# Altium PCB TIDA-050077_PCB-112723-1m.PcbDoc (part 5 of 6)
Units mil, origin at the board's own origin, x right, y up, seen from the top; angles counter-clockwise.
Board outline 3780 x 7750 mil, 16 copper layers (Top Layer, L2-Powet 1, L3-Power 2, L4-Power 3, L5-Power 4, L6-INT 1, L7-INT 2, L8-INT 3, L9-INT 4, L10-INT 5, L11-INT 6, L12-Power 5, L13-Power 6, L14-Power 7, L15-Power 8, Bottom Layer), stack 121.442 mil thick; 381 components, 136 nets, 958 pads, 3470 vias.
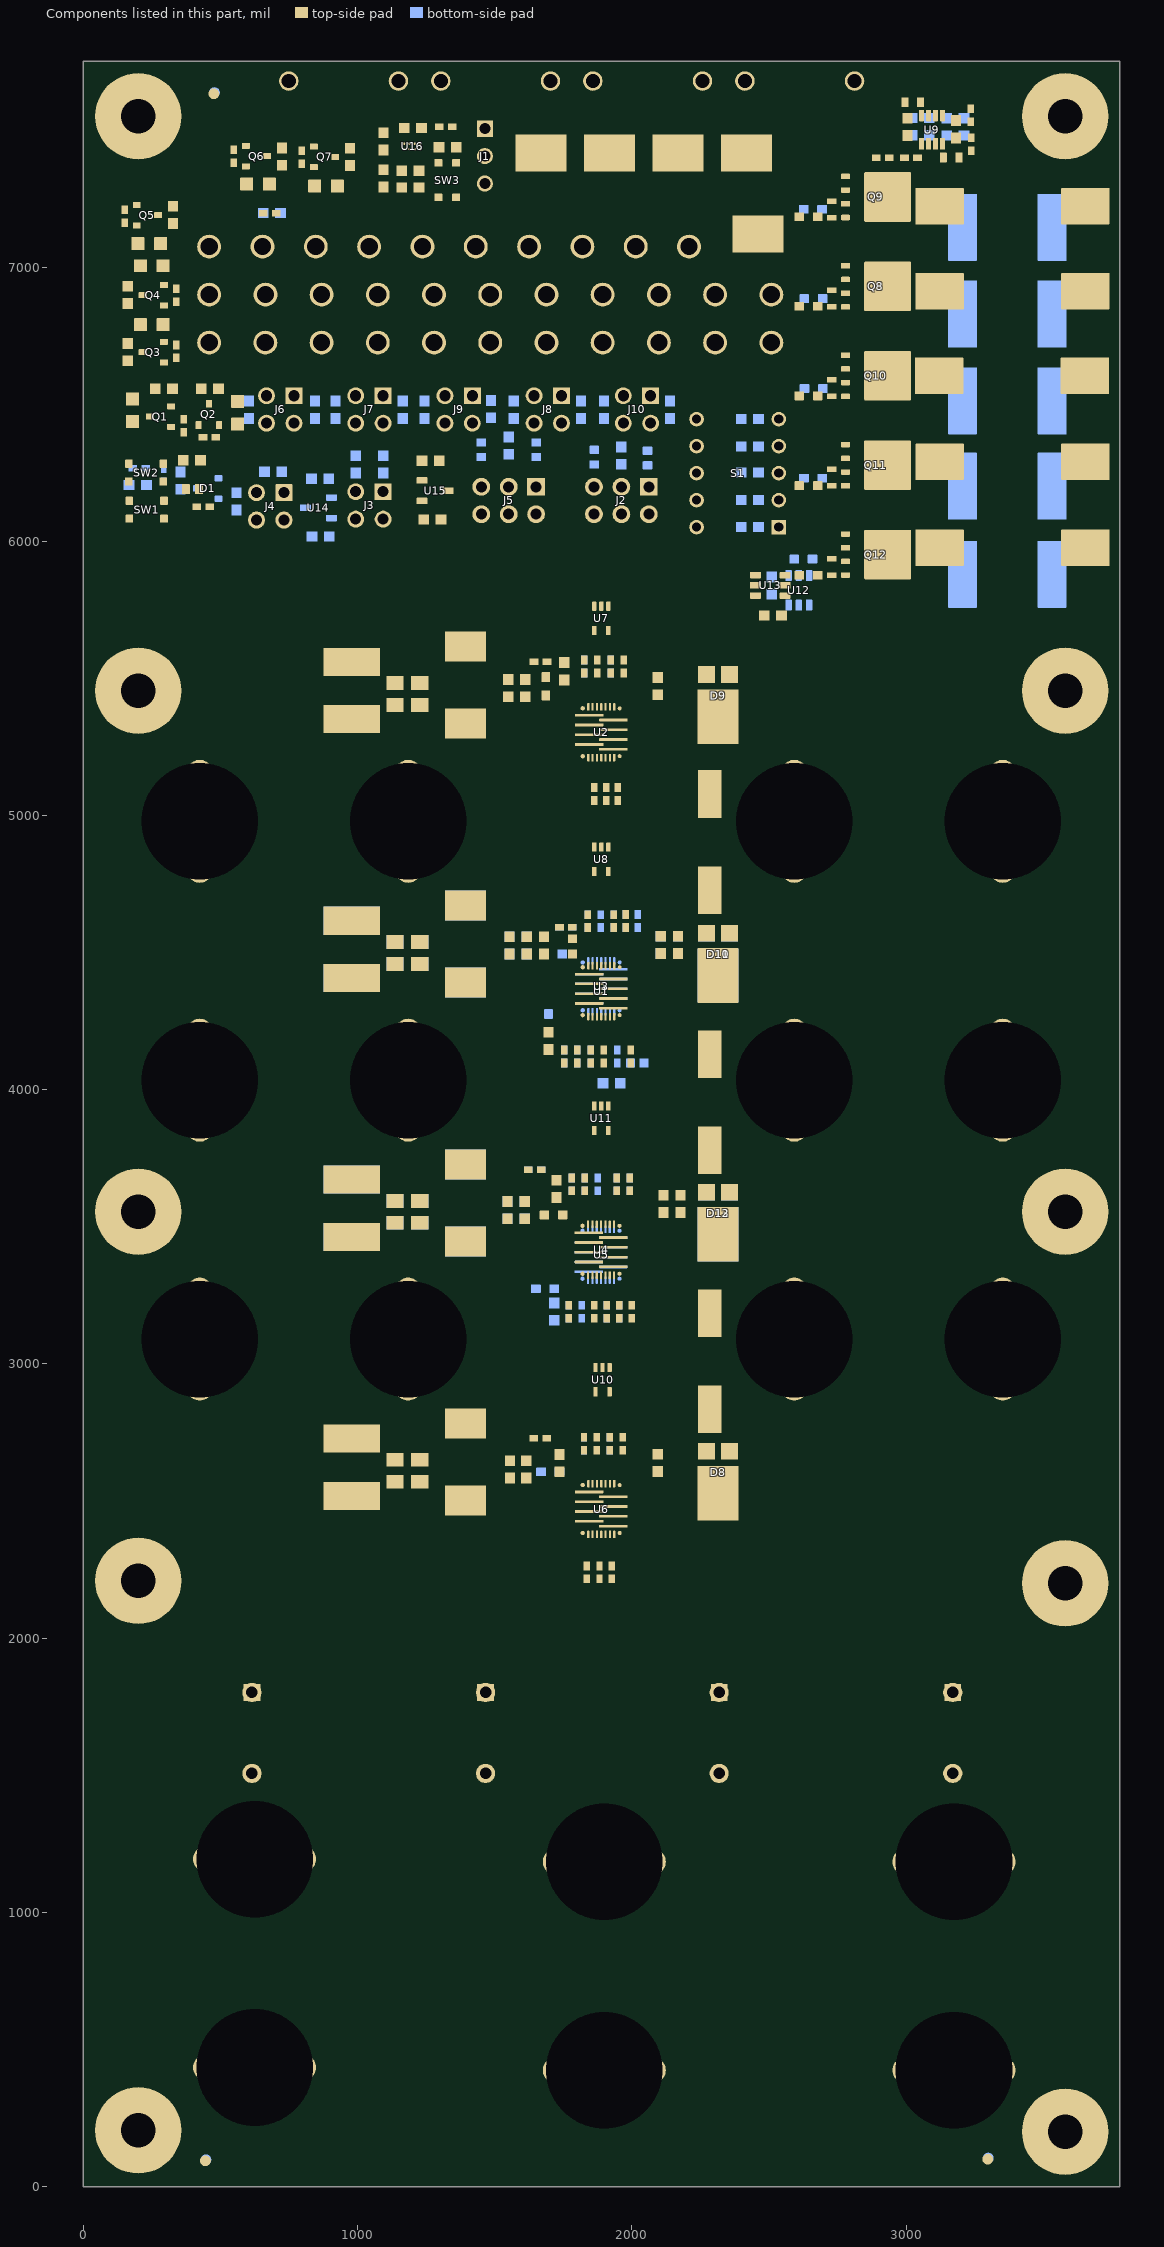
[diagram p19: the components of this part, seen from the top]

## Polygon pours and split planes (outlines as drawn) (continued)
VOUT on L6-INT 1 "NONET_L-01_P-001" (solid, pour order 1728): 1904.38,4431.31 1904.38,4304.44 1921.96,4286.87 2002.31,4286.87 2060.99,4228.19 2231.91,4228.19 2263.2,4259.48 2263.2,4474.28 2238.11,4499.37 2046.07,4499.37 1995.98,4449.28 1922.35,4449.28
VIN on L6-INT 1 "NONET_L-01_P-001" (solid, pour order 1727): 1871.48,4290.26 1871.48,4417.13 1853.91,4434.7 1773.55,4434.7 1714.88,4493.38 1487.5,4493.38 1461.52,4467.39 1461.52,4252.8 1492.12,4222.2 1729.79,4222.2 1779.88,4272.29 1853.52,4272.29
VOUT on L6-INT 1 "NONET_L-01_P-001" (solid, pour order 1726): 1904.38,5375.51 1904.38,5248.64 1921.96,5231.06 2002.31,5231.06 2060.99,5172.39 2231.91,5172.39 2263.2,5203.67 2263.2,5418.48 2238.11,5443.56 2046.07,5443.56 1995.98,5393.48 1922.35,5393.48
VIN on L6-INT 1 "NONET_L-01_P-001" (solid, pour order 1725): 1871.48,5234.45 1871.48,5361.32 1853.91,5378.9 1773.55,5378.9 1714.88,5437.57 1487.5,5437.57 1461.52,5411.59 1461.52,5197 1492.12,5166.4 1729.79,5166.4 1779.88,5216.49 1853.52,5216.49
CSA_IN- on L6-INT 1 "L6-INT_1_CSA_IN-_P1611" (solid, remove dead copper, pour order 1611): 3332.59,5884.82 3304.22,5856.44 2882.86,5856.44 2858.8,5880.5 2858.8,7380.82 2873.03,7395.05 3312.43,7395.05 3332.59,7374.88
PGND on Bottom Layer "BOTTOM_LAYER_PGND_P1687" (solid, remove dead copper, pour order 1687): 3684.32,28.94 84.24,28.94 24.73,88.44 24.73,1655.4 79.8,1710.46 3679.91,1710.46 3734.56,1655.82 3734.56,79.17
QGND on Bottom Layer "BOTTOM_LAYER_QGND_P1690" (solid, remove dead copper, pour order 1690): 61.55,7507.56 278.5,7724.51 3562.52,7724.51 3754.51,7532.52 3754.51,5837.9 3631.17,5714.55 2703.25,5714.55 2393.46,6024.34 200.18,6024.34 61.55,6162.97
VIN on Bottom Layer "NONET_L-01_P-001" (solid, remove dead copper, pour order 1865): 33.94,5984.68 73.16,6023.9 1791.9,6023.9 1869.84,5945.95 1869.84,1794.46 1814.28,1738.9 79.28,1738.9 34.28,1783.9 34.28,1793.9 33.94,1794.24
VOUT on Bottom Layer "NONET_L-01_P-001" (solid, remove dead copper, pour order 1866): 3746.33,5668.2 3707.33,5707.2 2455.94,5707.2 2264.13,5899.02 1938.03,5899.02 1907.68,5869.43 1907.68,1796.21 1965,1738.9 3669.28,1738.9 3746.33,1815.95
PGND on Bottom Layer "BOTTOM_LAYER_PGND_P1686" (solid, remove dead copper, pour order 1686): 2679.5,7378.31 2791.4,7378.31 2827.22,7342.49 2827.22,5758.47 2812.04,5743.29 2597.74,5743.29 2594.49,5746.54 2594.49,5785.95 2596.74,5788.2 2649.05,5788.2 2668.59,5807.75 2668.59,7367.4
VOUT on Bottom Layer "NONET_L-01_P-001" (solid, remove dead copper, pour order 1862): 2004.95,5235.53 2039.3,5201.18 2377.66,5201.18 2403.85,5227.37 2403.85,5444.22 2387.76,5460.31 2073.05,5460.31 1986.84,5374.1 1912.93,5374.1 1907.68,5368.85 1907.68,5240.87 1913.03,5235.53
VOUT on Bottom Layer "BOTTOM_LAYER_VOUT_P1861" (solid, remove dead copper, pour order 1861): 2039.17,5201.31 2376.92,5201.31 2403.85,5228.23 2403.85,5444.22 2387.76,5460.31 2073.05,5460.31 1986.84,5374.15 1912.54,5374.15 1907.88,5369.49 1907.88,5240.68 1913.03,5235.53 2004.95,5235.53
VOUT on Bottom Layer "BOTTOM_LAYER_VOUT_P1860" (solid, remove dead copper, pour order 1860): 1986.84,5374.1 2072.39,5459.65 2145.31,5459.65 2173.3,5431.66 2173.3,5234.55 2139.92,5201.18 2039.04,5201.18 2004.49,5235.73 1913.03,5235.53 1907.88,5240.68 1907.88,5369.49 1912.48,5374.1
VOUT on Bottom Layer "NONET_L-01_P-001" (solid, remove dead copper, pour order 1859): 2004.95,2402.94 2039.3,2368.59 2377.66,2368.59 2403.85,2394.78 2403.85,2611.63 2387.76,2627.72 2073.05,2627.72 1986.84,2541.51 1912.93,2541.51 1907.68,2536.27 1907.68,2408.29 1913.03,2402.94
VOUT on Bottom Layer "BOTTOM_LAYER_VOUT_P1858" (solid, remove dead copper, pour order 1858): 2039.17,2368.72 2376.92,2368.72 2403.85,2395.65 2403.85,2611.63 2387.76,2627.72 2073.05,2627.72 1986.84,2541.56 1912.54,2541.56 1907.88,2536.91 1907.88,2408.09 1913.03,2402.94 2004.95,2402.94
VOUT on Bottom Layer "BOTTOM_LAYER_VOUT_P1857" (solid, remove dead copper, pour order 1857): 1986.84,2541.51 2072.39,2627.06 2145.31,2627.06 2173.3,2599.08 2173.3,2401.96 2139.92,2368.59 2039.04,2368.59 2004.49,2403.14 1913.03,2402.94 1907.88,2408.09 1907.88,2536.91 1912.48,2541.51
VOUT on Bottom Layer "NONET_L-01_P-001" (solid, remove dead copper, pour order 1850): 2389.2,3573.5 2091.46,3573.5 1985.25,3467.29 1914.94,3467.29 1907.78,3460.13 1907.78,3330.43 1909.89,3328.32 1990.14,3328.32 2094.28,3224.17 2094.28,3096.7 2134.21,3056.77 2364.38,3056.77 2403.95,3096.34 2403.95,3558.75
VOUT on Bottom Layer "BOTTOM_LAYER_VOUT_P1849" (solid, remove dead copper, pour order 1849): 2039.27,3279.18 2377.02,3279.18 2403.95,3306.11 2403.95,3562.28 2392.62,3573.61 2092.02,3573.61 1985.29,3466.95 1914.61,3466.95 1907.98,3460.31 1907.98,3330.23 1909.89,3328.32 1990.14,3328.32
VOUT on Bottom Layer "BOTTOM_LAYER_VOUT_P1848" (solid, remove dead copper, pour order 1848): 2002.4,3467.43 2072.49,3537.52 2145.41,3537.52 2173.4,3509.53 2173.4,3312.42 2140.02,3279.05 2039.14,3279.05 1989.72,3328.47 1909.91,3328.3 1907.98,3330.23 1907.98,3460.21 1915.2,3467.43
VOUT on Bottom Layer "BOTTOM_LAYER_VOUT_P1842" (solid, remove dead copper, pour order 1842): 2002.3,4445.36 2072.39,4515.45 2145.31,4515.45 2173.3,4487.47 2173.3,4290.36 2139.92,4256.98 2039.04,4256.98 1989.62,4306.41 1909.81,4306.23 1907.88,4308.17 1907.88,4438.14 1915.1,4445.36
VOUT on Bottom Layer "NONET_L-01_P-001" (solid, remove dead copper, pour order 1844): 2387.76,4516.11 2073.05,4516.11 2002.16,4445.22 1914.84,4445.22 1907.68,4438.07 1907.68,4308.36 1909.79,4306.25 1990.04,4306.25 2094.18,4202.1 2094.18,4074.63 2134.11,4034.7 2364.28,4034.7 2403.85,4074.27 2403.85,4500.02
VOUT on Bottom Layer "BOTTOM_LAYER_VOUT_P1843" (solid, remove dead copper, pour order 1843): 2039.17,4257.11 2376.92,4257.11 2403.85,4284.04 2403.85,4500.02 2387.76,4516.11 2073.05,4516.11 2001.78,4444.88 1914.51,4444.88 1907.88,4438.24 1907.88,4308.17 1909.79,4306.25 1990.04,4306.25
VIN on Bottom Layer "NONET_L-01_P-001" (solid, pour order 1832): 18 vertices, not listed, extent 1451,2359.04 1869.65,2625.06
VIN on Bottom Layer "BOTTOM_LAYER_VIN_P1831" (solid, remove dead copper, pour order 1831): 1785.72,2541.28 1756.66,2570.34 1641.82,2570.34 1625.35,2553.87 1625.35,2374.27 1640.58,2359.04 1728.93,2359.04 1770.05,2400.16 1867.67,2399.94 1869.65,2401.93 1869.65,2538.67 1867.04,2541.28
VIN on Bottom Layer "NONET_L-01_P-001" (solid, pour order 1830): 1866.01,5231.24 1768.22,5231.24 1728.93,5191.94 1728.93,5191.63 1486.55,5191.63 1451,5227.17 1451,5378.71 1486.19,5413.9 1745.68,5413.9 1785.72,5373.86 1867.04,5373.86 1869.65,5371.26 1869.65,5234.87
VIN on Bottom Layer "BOTTOM_LAYER_VIN_P1829" (solid, remove dead copper, pour order 1829): 17 vertices, not listed, extent 875.36,3302.93 1869.65,3550.07
VIN on Bottom Layer "BOTTOM_LAYER_VIN_P1828" (solid, remove dead copper, pour order 1828): 1785.65,3472.07 1743.19,3514.53 1641.82,3514.53 1625.35,3498.06 1625.35,3318.46 1640.58,3303.23 1728.93,3303.23 1753.55,3327.85 1863.2,3327.61 1869.65,3334.06 1869.65,3467.78 1865.36,3472.07
VIN on Bottom Layer "BOTTOM_LAYER_VIN_P1827" (solid, remove dead copper, pour order 1827): 17 vertices, not listed, extent 875.36,4247.13 1869.65,4515.88
VIN on Bottom Layer "BOTTOM_LAYER_VIN_P1826" (solid, remove dead copper, pour order 1826): 1777.39,4429.67 1748.33,4458.73 1641.82,4458.73 1625.35,4442.26 1625.35,4262.66 1640.58,4247.43 1728.93,4247.43 1787.96,4306.46 1868.1,4306.29 1869.65,4307.83 1869.65,4427.06 1867.04,4429.67
VIN on Bottom Layer "BOTTOM_LAYER_VIN_P1825" (solid, remove dead copper, pour order 1825): 1785.72,5373.86 1756.66,5402.93 1641.82,5402.93 1625.35,5386.45 1625.35,5206.86 1640.58,5191.63 1728.93,5191.63 1768.75,5231.45 1866.37,5231.24 1869.65,5234.51 1869.65,5371.26 1867.04,5373.86
CSA_IN- on Bottom Layer "v" (solid, remove dead copper, pour order 1685): 2882.44,5750.2 2871.33,5750.2 2842.98,5778.55 2842.98,7309.55 2884.24,7350.81 3263.1,7350.81 3271.05,7342.86 3271.05,5763.76 3257.49,5750.2
+5V on Bottom Layer "BOTTOM_LAYER_+5V_P1340" (solid, remove dead copper, pour order 1340): 1200.29,6179.5 1215.72,6194.93 1215.72,6261.82 1202.46,6275.08 1155.91,6275.08 1148.94,6268.11 1148.94,6186 1155.44,6179.5
QGND on L8-INT 3 "L8-INT_3_QGND_P1756" (solid, remove dead copper, pour order 1756): 20 vertices, not listed, extent 32.15,2073.9 3388.65,7724.51
PGND on L8-INT 3 "L8-INT_3_PGND_P1753" (solid, remove dead copper, pour order 1753): 72.4,1690.9 3683.4,1690.9 3742.95,1631.34 3742.95,62.57 3709.28,28.9 59.06,28.9 30.45,57.51 30.45,1648.95
VIN on L8-INT 3 "NONET_L-01_P-001" (solid, remove dead copper, pour order 1754): 1843.02,1723.9 93.76,1723.9 36.07,1781.59 36.07,5987.28 64.69,6015.91 900.83,6015.91 1246.7,5670.03 1246.7,2187.78 1385.58,2048.9 1845.75,2048.9 1873.32,2021.32 1873.32,1754.2
VOUT on L8-INT 3 "NONET_L-01_P-001" (solid, remove dead copper, pour order 1755): 1928.41,1723.9 3664.89,1723.9 3748.72,1807.73 3748.72,5771.35 3712.9,5807.18 2903.87,5807.18 2519.28,5422.59 2519.28,2149.07 2419.11,2048.9 1926.3,2048.9 1904.28,2026.88 1904.28,1748.03
VOUT on L8-INT 3 "L8-INT_3_VOUT_P1752" (solid, remove dead copper, pour order 1752): 3295.05,5820.24 3264.28,5851.01 3264.28,7435.56 3279.45,7450.73 3712.58,7450.73 3730.48,7432.83 3730.48,5853.16 3697.57,5820.24
VOUT on L8-INT 3 "NONET_L-01_P-001" (solid, pour order 1629): 1904.38,3487.12 1904.38,3360.24 1921.96,3342.67 2002.31,3342.67 2060.99,3284 2231.91,3284 2263.2,3315.28 2263.2,3530.08 2238.11,3555.17 2046.07,3555.17 1995.98,3505.08 1922.35,3505.08
CSA_IN- on L8-INT 3 "L8-INT_3_CSA_IN-_P1750" (solid, remove dead copper, pour order 1750): 2830.33,7381.78 2864.89,7416.34 3182.11,7416.34 3234.84,7363.6 3234.84,5904.85 3234.84,5893.14 3201.04,5859.33 2852.73,5859.33 2830.33,5881.73
VIN on L8-INT 3 "NONET_L-01_P-001" (solid, pour order 1628): 1871.48,3346.06 1871.48,3472.93 1853.91,3490.51 1773.55,3490.51 1714.88,3549.18 1487.5,3549.18 1461.52,3523.2 1461.52,3308.61 1492.12,3278.01 1729.79,3278.01 1779.88,3328.09 1853.52,3328.09
VIN on L8-INT 3 "NONET_L-01_P-001" (solid, pour order 1624): 1871.48,5234.45 1871.48,5361.32 1853.91,5378.9 1773.55,5378.9 1714.88,5437.57 1487.5,5437.57 1461.52,5411.59 1461.52,5197 1492.12,5166.4 1729.79,5166.4 1779.88,5216.49 1853.52,5216.49
VOUT on L8-INT 3 "NONET_L-01_P-001" (solid, pour order 1749): 1904.38,2542.92 1904.38,2416.05 1921.96,2398.48 2002.31,2398.48 2060.99,2339.8 2231.91,2339.8 2263.2,2371.09 2263.2,2585.89 2238.11,2610.98 2046.07,2610.98 1995.98,2560.89 1922.35,2560.89
VIN on L8-INT 3 "NONET_L-01_P-001" (solid, pour order 1630): 1871.48,2401.86 1871.48,2528.74 1853.91,2546.31 1773.55,2546.31 1714.88,2604.98 1487.5,2604.98 1461.52,2579 1461.52,2364.41 1492.12,2333.81 1729.79,2333.81 1779.88,2383.9 1853.52,2383.9
VOUT on L8-INT 3 "NONET_L-01_P-001" (solid, pour order 1627): 1904.38,4431.31 1904.38,4304.44 1921.96,4286.87 2002.31,4286.87 2060.99,4228.19 2231.91,4228.19 2263.2,4259.48 2263.2,4474.28 2238.11,4499.37 2046.07,4499.37 1995.98,4449.28 1922.35,4449.28
VIN on L8-INT 3 "NONET_L-01_P-001" (solid, pour order 1626): 1871.48,4290.26 1871.48,4417.13 1853.91,4434.7 1773.55,4434.7 1714.88,4493.38 1487.5,4493.38 1461.52,4467.39 1461.52,4252.8 1492.12,4222.2 1729.79,4222.2 1779.88,4272.29 1853.52,4272.29
VOUT on L8-INT 3 "NONET_L-01_P-001" (solid, pour order 1625): 1904.38,5375.51 1904.38,5248.64 1921.96,5231.06 2002.31,5231.06 2060.99,5172.39 2231.91,5172.39 2263.2,5203.67 2263.2,5418.48 2238.11,5443.56 2046.07,5443.56 1995.98,5393.48 1922.35,5393.48
PGND on L8-INT 3 "L8-INT_3_PGND_P1751" (solid, remove dead copper, pour order 1751): 2812.27,5933.3 2802.72,5923.76 2659.73,5923.76 2646,5937.49 2646,7377.51 2661.6,7393.1 2802.45,7393.1 2812.27,7383.28
QGND on L2-Powet 1 "L2-POWET_1_QGND_P1588" (solid, remove dead copper, pour order 1588): 3405.67,7441.67 3405.67,7692.51 3373.67,7724.51 229.89,7724.51 34.28,7528.9 34.28,6139.85 122.53,6051.6 2562.57,6051.6 2644.28,6133.31 2644.28,7385.74 2669.86,7411.32 3375.32,7411.32
PGND on L2-Powet 1 "NONET_L-01_P-001" (solid, remove dead copper, pour order 1815): 88.28,6038.29 2560.87,6038.29 2768.57,5830.59 3199.03,5830.59 3272.92,5756.7 3703.33,5756.7 3746.33,5713.7 3746.33,64.32 3710.91,28.9 82.38,28.9 33.94,77.34 33.94,5984.68
VOUT on L2-Powet 1 "L2-POWET_1_VOUT_P1584" (solid, remove dead copper, pour order 1584): 3295.94,7378.5 3717.7,7378.5 3746.33,7349.87 3746.33,5797.42 3715.84,5766.92 3307.15,5766.92 3279.28,5794.79 3279.28,7361.85
VOUT on L2-Powet 1 "L8_BOT_[PWR]_NONET_P-001" (solid, remove dead copper, pour order 1370): 3407.49,3323.9 3407.49,2867.47 3372.2,2832.18 2581.76,2832.18 2539.6,2874.34 2539.6,3328.09 2570.4,3358.9 3372.49,3358.9
VIN on L2-Powet 1 "L8_BOT_[PWR]_NONET_P-001" (solid, remove dead copper, pour order 1369): 369.28,2860.51 369.28,3316.93 404.58,3352.23 1195.02,3352.23 1237.18,3310.07 1237.18,2856.31 1206.37,2825.51 404.28,2825.51
VOUT on L2-Powet 1 "NONET_L-01_P-001" (solid, pour order 1706): 1904.38,3487.12 1904.38,3360.24 1921.96,3342.67 2002.31,3342.67 2060.99,3284 2231.91,3284 2263.2,3315.28 2263.2,3530.08 2238.11,3555.17 2046.07,3555.17 1995.98,3505.08 1922.35,3505.08
VIN on L2-Powet 1 "L8_BOT_[PWR]_NONET_P-001" (solid, remove dead copper, pour order 1367): 369.28,4715.9 369.28,5178.04 416.86,5225.62 1195.02,5225.62 1237.18,5183.46 1237.18,4729.7 1206.37,4698.9 386.28,4698.9
PGND on L2-Powet 1 "L2-POWET_1_PGND_P1586" (solid, remove dead copper, pour order 1586): 2832.71,5950.81 2825.33,5943.43 2665.36,5943.43 2658.2,5950.59 2658.2,7383.68 2674.25,7399.73 2814.57,7399.73 2832.71,7381.59
VOUT on L2-Powet 1 "NONET_L-01_P-001" (solid, pour order 1708): 1904.38,2542.92 1904.38,2416.05 1921.96,2398.48 2002.31,2398.48 2060.99,2339.8 2231.91,2339.8 2263.2,2371.09 2263.2,2585.89 2238.11,2610.98 2046.07,2610.98 1995.98,2560.89 1922.35,2560.89
VIN on L2-Powet 1 "NONET_L-01_P-001" (solid, pour order 1707): 1871.48,2401.86 1871.48,2528.74 1853.91,2546.31 1773.55,2546.31 1714.88,2604.98 1487.5,2604.98 1461.52,2579 1461.52,2364.41 1492.12,2333.81 1729.79,2333.81 1779.88,2383.9 1853.52,2383.9
VIN on L2-Powet 1 "NONET_L-01_P-001" (solid, pour order 1705): 1871.48,3346.06 1871.48,3472.93 1853.91,3490.51 1773.55,3490.51 1714.88,3549.18 1487.5,3549.18 1461.52,3523.2 1461.52,3308.61 1492.12,3278.01 1729.79,3278.01 1779.88,3328.09 1853.52,3328.09
VOUT on L2-Powet 1 "NONET_L-01_P-001" (solid, pour order 1704): 1904.38,4431.31 1904.38,4304.44 1921.96,4286.87 2002.31,4286.87 2060.99,4228.19 2231.91,4228.19 2263.2,4259.48 2263.2,4474.28 2238.11,4499.37 2046.07,4499.37 1995.98,4449.28 1922.35,4449.28
VIN on L2-Powet 1 "NONET_L-01_P-001" (solid, pour order 1703): 1871.48,4290.26 1871.48,4417.13 1853.91,4434.7 1773.55,4434.7 1714.88,4493.38 1487.5,4493.38 1461.52,4467.39 1461.52,4252.8 1492.12,4222.2 1729.79,4222.2 1779.88,4272.29 1853.52,4272.29
VOUT on L2-Powet 1 "NONET_L-01_P-001" (solid, pour order 1702): 1904.38,5375.51 1904.38,5248.64 1921.96,5231.06 2002.31,5231.06 2060.99,5172.39 2231.91,5172.39 2263.2,5203.67 2263.2,5418.48 2238.11,5443.56 2046.07,5443.56 1995.98,5393.48 1922.35,5393.48
VIN on L2-Powet 1 "NONET_L-01_P-001" (solid, pour order 1701): 1871.48,5234.45 1871.48,5361.32 1853.91,5378.9 1773.55,5378.9 1714.88,5437.57 1487.5,5437.57 1461.52,5411.59 1461.52,5197 1492.12,5166.4 1729.79,5166.4 1779.88,5216.49 1853.52,5216.49
CSA_IN- on L2-Powet 1 "L2-POWET_1_CSA_IN-_P1585" (solid, remove dead copper, pour order 1585): 3263.32,5880.3 3229.51,5846.5 2881.2,5846.5 2858.8,5868.9 2858.8,7383.14 2869.43,7393.77 3240.95,7393.77 3263.32,7371.4
VOUT on L2-Powet 1 "L8_BOT_[PWR]_NONET_P-001" (solid, remove dead copper, pour order 1373): 3407.49,5212.29 3407.49,4755.86 3372.2,4720.57 2581.76,4720.57 2539.6,4762.73 2539.6,5216.49 2570.4,5247.29 3372.49,5247.29
VOUT on L2-Powet 1 "L8_BOT_[PWR]_NONET_P-001" (solid, remove dead copper, pour order 1371): 3407.49,4268.09 3407.49,3811.67 3372.2,3776.37 2581.76,3776.37 2539.6,3818.53 2539.6,4272.29 2570.4,4303.09 3372.49,4303.09
VIN on L2-Powet 1 "L8_BOT_[PWR]_NONET_P-001" (solid, remove dead copper, pour order 1368): 369.28,3804.7 369.28,4261.13 404.58,4296.42 1195.02,4296.42 1237.18,4254.26 1237.18,3800.51 1206.37,3769.7 404.28,3769.7
QGND on L3-Power 2 "L3-POWER_2_QGND_P1595" (solid, remove dead copper, pour order 1595): 3332.59,7413.9 3386.33,7467.64 3386.33,7716.2 3378.02,7724.51 226.93,7724.51 29.23,7526.81 29.23,6081.96 82.37,6031.04 2585.13,6031.04 2654.12,6100.03 2654.12,7391.34 2676.68,7413.9
PGND on L3-Power 2 "L3-POWER_2_PGND_P1594" (solid, remove dead copper, pour order 1594): 26.96,56.7 55.66,28 3703.56,28 3746.15,70.6 3746.15,1660.54 3715.79,1690.9 48.73,1690.9 26.96,1669.12
VIN on L3-Power 2 "L3-POWER_2_VIN_P1817" (solid, remove dead copper, pour order 1817): 76.04,1723.9 1835.41,1723.9 1873.32,1761.8 1873.32,5995.34 1850.52,6018.73 73.45,6018.73 28.38,5973.66 28.38,1771.56
VOUT on L3-Power 2 "L3-POWER_2_VOUT_P1816" (solid, remove dead copper, pour order 1816): 1931.67,6018 2533.6,6018 2737.97,5813.63 3701.12,5813.63 3753.65,5761.09 3753.65,1751.37 3726.18,1723.9 1941.76,1723.9 1904.28,1761.37 1904.28,5990.62
VOUT on L3-Power 2 "L3-POWER_2_VOUT_P1589" (solid, remove dead copper, pour order 1589): 3380.94,7387.36 3721.81,7387.36 3744.28,7364.89 3744.28,5854.53 3713.49,5823.73 3391.9,5823.73 3359.28,5856.35 3359.28,7365.7
VOUT on L3-Power 2 "NONET_L-01_P-001" (solid, pour order 1714): 1904.38,3487.12 1904.38,3360.24 1921.96,3342.67 2002.31,3342.67 2060.99,3284 2231.91,3284 2263.2,3315.28 2263.2,3530.08 2238.11,3555.17 2046.07,3555.17 1995.98,3505.08 1922.35,3505.08
PGND on L3-Power 2 "L3-POWER_2_PGND_P1591" (solid, remove dead copper, pour order 1591): 2843.98,5931.08 2823.92,5911.02 2681.1,5911.02 2669.47,5922.65 2669.47,7376.14 2688.81,7395.49 2821.74,7395.49 2843.98,7373.25
VOUT on L3-Power 2 "NONET_L-01_P-001" (solid, pour order 1716): 1904.38,2542.92 1904.38,2416.05 1921.96,2398.48 2002.31,2398.48 2060.99,2339.8 2231.91,2339.8 2263.2,2371.09 2263.2,2585.89 2238.11,2610.98 2046.07,2610.98 1995.98,2560.89 1922.35,2560.89
VIN on L3-Power 2 "NONET_L-01_P-001" (solid, pour order 1715): 1871.48,2401.86 1871.48,2528.74 1853.91,2546.31 1773.55,2546.31 1714.88,2604.98 1487.5,2604.98 1461.52,2579 1461.52,2364.41 1492.12,2333.81 1729.79,2333.81 1779.88,2383.9 1853.52,2383.9
VIN on L3-Power 2 "NONET_L-01_P-001" (solid, pour order 1713): 1871.48,3346.06 1871.48,3472.93 1853.91,3490.51 1773.55,3490.51 1714.88,3549.18 1487.5,3549.18 1461.52,3523.2 1461.52,3308.61 1492.12,3278.01 1729.79,3278.01 1779.88,3328.09 1853.52,3328.09
VOUT on L3-Power 2 "NONET_L-01_P-001" (solid, pour order 1712): 1904.38,4431.31 1904.38,4304.44 1921.96,4286.87 2002.31,4286.87 2060.99,4228.19 2231.91,4228.19 2263.2,4259.48 2263.2,4474.28 2238.11,4499.37 2046.07,4499.37 1995.98,4449.28 1922.35,4449.28
VIN on L3-Power 2 "NONET_L-01_P-001" (solid, pour order 1711): 1871.48,4290.26 1871.48,4417.13 1853.91,4434.7 1773.55,4434.7 1714.88,4493.38 1487.5,4493.38 1461.52,4467.39 1461.52,4252.8 1492.12,4222.2 1729.79,4222.2 1779.88,4272.29 1853.52,4272.29
VOUT on L3-Power 2 "NONET_L-01_P-001" (solid, pour order 1710): 1904.38,5375.51 1904.38,5248.64 1921.96,5231.06 2002.31,5231.06 2060.99,5172.39 2231.91,5172.39 2263.2,5203.67 2263.2,5418.48 2238.11,5443.56 2046.07,5443.56 1995.98,5393.48 1922.35,5393.48
VIN on L3-Power 2 "NONET_L-01_P-001" (solid, pour order 1709): 1871.48,5234.45 1871.48,5361.32 1853.91,5378.9 1773.55,5378.9 1714.88,5437.57 1487.5,5437.57 1461.52,5411.59 1461.52,5197 1492.12,5166.4 1729.79,5166.4 1779.88,5216.49 1853.52,5216.49
CSA_IN- on L3-Power 2 "L3-POWER_2_CSA_IN-_P1590" (solid, remove dead copper, pour order 1590): 3332.59,5884.82 3304.22,5856.44 2882.86,5856.44 2858.8,5880.5 2858.8,7380.82 2873.03,7395.05 3312.43,7395.05 3332.59,7374.88
QGND on L7-INT 2 "L7-INT_2_QGND_P1748" (solid, remove dead copper, pour order 1748): 20 vertices, not listed, extent 32.15,2073.9 3388.03,7724.51
PGND on L7-INT 2 "L7-INT_2_PGND_P1745" (solid, remove dead copper, pour order 1745): 72.4,1690.9 3683.4,1690.9 3742.95,1631.34 3742.95,62.57 3709.28,28.9 59.06,28.9 30.45,57.51 30.45,1648.95
VIN on L7-INT 2 "NONET_L-01_P-001" (solid, remove dead copper, pour order 1746): 1843.02,1723.9 93.76,1723.9 36.07,1781.59 36.07,5987.28 64.69,6015.91 900.83,6015.91 1246.7,5670.03 1246.7,2187.78 1385.58,2048.9 1845.75,2048.9 1873.32,2021.32 1873.32,1754.2
VOUT on L7-INT 2 "NONET_L-01_P-001" (solid, remove dead copper, pour order 1747): 1928.41,1723.9 3664.89,1723.9 3748.72,1807.73 3748.72,5771.35 3712.9,5807.18 2903.87,5807.18 2519.28,5422.59 2519.28,2149.07 2419.11,2048.9 1926.3,2048.9 1904.28,2026.88 1904.28,1748.03
VOUT on L7-INT 2 "L7-INT_2_VOUT_P1744" (solid, remove dead copper, pour order 1744): 3295.05,5820.24 3264.28,5851.01 3264.28,7435.56 3279.45,7450.73 3712.58,7450.73 3730.48,7432.83 3730.48,5853.16 3697.57,5820.24
VOUT on L7-INT 2 "NONET_L-01_P-001" (solid, pour order 1622): 1904.38,3487.12 1904.38,3360.24 1921.96,3342.67 2002.31,3342.67 2060.99,3284 2231.91,3284 2263.2,3315.28 2263.2,3530.08 2238.11,3555.17 2046.07,3555.17 1995.98,3505.08 1922.35,3505.08
CSA_IN- on L7-INT 2 "L7-INT_2_CSA_IN-_P1742" (solid, remove dead copper, pour order 1742): 2830.33,7381.78 2891.69,7443.15 3228.76,7443.15 3234.84,7437.06 3234.84,5904.85 3234.84,5893.14 3201.04,5859.33 2852.73,5859.33 2830.33,5881.73
VIN on L7-INT 2 "NONET_L-01_P-001" (solid, pour order 1623): 1871.48,2401.86 1871.48,2528.74 1853.91,2546.31 1773.55,2546.31 1714.88,2604.98 1487.5,2604.98 1461.52,2579 1461.52,2364.41 1492.12,2333.81 1729.79,2333.81 1779.88,2383.9 1853.52,2383.9
VOUT on L7-INT 2 "NONET_L-01_P-001" (solid, pour order 1741): 1904.38,2542.92 1904.38,2416.05 1921.96,2398.48 2002.31,2398.48 2060.99,2339.8 2231.91,2339.8 2263.2,2371.09 2263.2,2585.89 2238.11,2610.98 2046.07,2610.98 1995.98,2560.89 1922.35,2560.89
VIN on L7-INT 2 "NONET_L-01_P-001" (solid, pour order 1621): 1871.48,3346.06 1871.48,3472.93 1853.91,3490.51 1773.55,3490.51 1714.88,3549.18 1487.5,3549.18 1461.52,3523.2 1461.52,3308.61 1492.12,3278.01 1729.79,3278.01 1779.88,3328.09 1853.52,3328.09
VOUT on L7-INT 2 "NONET_L-01_P-001" (solid, pour order 1620): 1904.38,4431.31 1904.38,4304.44 1921.96,4286.87 2002.31,4286.87 2060.99,4228.19 2231.91,4228.19 2263.2,4259.48 2263.2,4474.28 2238.11,4499.37 2046.07,4499.37 1995.98,4449.28 1922.35,4449.28
VIN on L7-INT 2 "NONET_L-01_P-001" (solid, pour order 1619): 1871.48,4290.26 1871.48,4417.13 1853.91,4434.7 1773.55,4434.7 1714.88,4493.38 1487.5,4493.38 1461.52,4467.39 1461.52,4252.8 1492.12,4222.2 1729.79,4222.2 1779.88,4272.29 1853.52,4272.29
VOUT on L7-INT 2 "NONET_L-01_P-001" (solid, pour order 1618): 1904.38,5375.51 1904.38,5248.64 1921.96,5231.06 2002.31,5231.06 2060.99,5172.39 2231.91,5172.39 2263.2,5203.67 2263.2,5418.48 2238.11,5443.56 2046.07,5443.56 1995.98,5393.48 1922.35,5393.48
VIN on L7-INT 2 "NONET_L-01_P-001" (solid, pour order 1617): 1871.48,5234.45 1871.48,5361.32 1853.91,5378.9 1773.55,5378.9 1714.88,5437.57 1487.5,5437.57 1461.52,5411.59 1461.52,5197 1492.12,5166.4 1729.79,5166.4 1779.88,5216.49 1853.52,5216.49
PGND on L7-INT 2 "L7-INT_2_PGND_P1743" (solid, remove dead copper, pour order 1743): 2812.27,5933.3 2802.72,5923.76 2659.73,5923.76 2646,5937.49 2646,7377.51 2661.6,7393.1 2802.45,7393.1 2812.27,7383.28
VOUT on L5-Power 4 "L5-POWER_4_VOUT_P1820" (solid, remove dead copper, pour order 1820): 1904.28,7664.49 1964.3,7724.51 3598.67,7724.51 3754.28,7568.9 3754.28,1748.9 3729.28,1723.9 1990.49,1723.9 1904.28,1810.1
PGND on L5-Power 4 "L5-POWER_4_PGND_P1426" (solid, remove dead copper, pour order 1426): 3714.28,1690.9 3754.51,1650.67 3754.51,60.72 3719.28,23.9 61.59,23.9 25.49,60 25.49,1636.16 80.22,1690.9
VIN on L5-Power 4 "L5-POWER_4_VIN_P1821" (solid, remove dead copper, pour order 1821): 25.49,7550.11 199.89,7724.51 1738.67,7724.51 1873.32,7589.86 1873.32,1827.18 1770.04,1723.9 81.62,1723.9 25.49,1780.03
VOUT on L5-Power 4 "NONET_L-01_P-001" (solid, pour order 1722): 1904.38,3487.12 1904.38,3360.24 1921.96,3342.67 2002.31,3342.67 2060.99,3284 2231.91,3284 2263.2,3315.28 2263.2,3530.08 2238.11,3555.17 2046.07,3555.17 1995.98,3505.08 1922.35,3505.08
VOUT on L5-Power 4 "NONET_L-01_P-001" (solid, pour order 1724): 1904.38,2542.92 1904.38,2416.05 1921.96,2398.48 2002.31,2398.48 2060.99,2339.8 2231.91,2339.8 2263.2,2371.09 2263.2,2585.89 2238.11,2610.98 2046.07,2610.98 1995.98,2560.89 1922.35,2560.89
VIN on L5-Power 4 "NONET_L-01_P-001" (solid, pour order 1723): 1871.48,2401.86 1871.48,2528.74 1853.91,2546.31 1773.55,2546.31 1714.88,2604.98 1487.5,2604.98 1461.52,2579 1461.52,2364.41 1492.12,2333.81 1729.79,2333.81 1779.88,2383.9 1853.52,2383.9
VIN on L5-Power 4 "NONET_L-01_P-001" (solid, pour order 1721): 1871.48,3346.06 1871.48,3472.93 1853.91,3490.51 1773.55,3490.51 1714.88,3549.18 1487.5,3549.18 1461.52,3523.2 1461.52,3308.61 1492.12,3278.01 1729.79,3278.01 1779.88,3328.09 1853.52,3328.09
VOUT on L5-Power 4 "NONET_L-01_P-001" (solid, pour order 1720): 1904.38,4431.31 1904.38,4304.44 1921.96,4286.87 2002.31,4286.87 2060.99,4228.19 2231.91,4228.19 2263.2,4259.48 2263.2,4474.28 2238.11,4499.37 2046.07,4499.37 1995.98,4449.28 1922.35,4449.28
VIN on L5-Power 4 "NONET_L-01_P-001" (solid, pour order 1719): 1871.48,4290.26 1871.48,4417.13 1853.91,4434.7 1773.55,4434.7 1714.88,4493.38 1487.5,4493.38 1461.52,4467.39 1461.52,4252.8 1492.12,4222.2 1729.79,4222.2 1779.88,4272.29 1853.52,4272.29
VOUT on L5-Power 4 "NONET_L-01_P-001" (solid, pour order 1718): 1904.38,5375.51 1904.38,5248.64 1921.96,5231.06 2002.31,5231.06 2060.99,5172.39 2231.91,5172.39 2263.2,5203.67 2263.2,5418.48 2238.11,5443.56 2046.07,5443.56 1995.98,5393.48 1922.35,5393.48
VIN on L5-Power 4 "NONET_L-01_P-001" (solid, pour order 1717): 1871.48,5234.45 1871.48,5361.32 1853.91,5378.9 1773.55,5378.9 1714.88,5437.57 1487.5,5437.57 1461.52,5411.59 1461.52,5197 1492.12,5166.4 1729.79,5166.4 1779.88,5216.49 1853.52,5216.49
QGND on L10-INT 5 "L10-INT_5_QGND_P1772" (solid, remove dead copper, pour order 1772): 3367.68,7413.9 3386.33,7432.55 3386.33,7711.85 3373.67,7724.51 226.93,7724.51 29.23,7526.81 29.23,6081.96 82.37,6031.04 2585.13,6031.04 2654.12,6100.03 2654.12,7391.34 2676.68,7413.9
PGND on L10-INT 5 "L10-INT_5_PGND_P1771" (solid, remove dead copper, pour order 1771): 26.96,56.7 55.66,28 3703.56,28 3746.15,70.6 3746.15,1660.54 3715.79,1690.9 48.73,1690.9 26.96,1669.12
VIN on L10-INT 5 "L10-INT_5_VIN_P1770" (solid, remove dead copper, pour order 1770): 76.04,1723.9 1835.41,1723.9 1873.32,1761.8 1873.32,5995.34 1850.52,6018.73 73.45,6018.73 28.38,5973.66 28.38,1771.56
VOUT on L10-INT 5 "L10-INT_5_VOUT_P1769" (solid, remove dead copper, pour order 1769): 1931.67,6018 2533.6,6018 2737.97,5813.63 3701.12,5813.63 3753.65,5761.09 3753.65,1751.37 3726.18,1723.9 1941.76,1723.9 1904.28,1761.37 1904.28,5990.62
VOUT on L10-INT 5 "L10-INT_5_VOUT_P1766" (solid, remove dead copper, pour order 1766): 3380.94,7387.36 3721.81,7387.36 3744.28,7364.89 3744.28,5854.53 3713.49,5823.73 3391.9,5823.73 3359.28,5856.35 3359.28,7365.7
VOUT on L10-INT 5 "NONET_L-01_P-001" (solid, pour order 1643): 1904.38,3487.12 1904.38,3360.24 1921.96,3342.67 2002.31,3342.67 2060.99,3284 2231.91,3284 2263.2,3315.28 2263.2,3530.08 2238.11,3555.17 2046.07,3555.17 1995.98,3505.08 1922.35,3505.08
PGND on L10-INT 5 "L10-INT_5_PGND_P1768" (solid, remove dead copper, pour order 1768): 2843.98,5931.08 2823.92,5911.02 2681.1,5911.02 2669.47,5922.65 2669.47,7376.14 2688.81,7395.49 2821.74,7395.49 2843.98,7373.25
VOUT on L10-INT 5 "NONET_L-01_P-001" (solid, pour order 1765): 1904.38,2542.92 1904.38,2416.05 1921.96,2398.48 2002.31,2398.48 2060.99,2339.8 2231.91,2339.8 2263.2,2371.09 2263.2,2585.89 2238.11,2610.98 2046.07,2610.98 1995.98,2560.89 1922.35,2560.89
VIN on L10-INT 5 "NONET_L-01_P-001" (solid, pour order 1644): 1871.48,2401.86 1871.48,2528.74 1853.91,2546.31 1773.55,2546.31 1714.88,2604.98 1487.5,2604.98 1461.52,2579 1461.52,2364.41 1492.12,2333.81 1729.79,2333.81 1779.88,2383.9 1853.52,2383.9
VIN on L10-INT 5 "NONET_L-01_P-001" (solid, pour order 1642): 1871.48,3346.06 1871.48,3472.93 1853.91,3490.51 1773.55,3490.51 1714.88,3549.18 1487.5,3549.18 1461.52,3523.2 1461.52,3308.61 1492.12,3278.01 1729.79,3278.01 1779.88,3328.09 1853.52,3328.09
VOUT on L10-INT 5 "NONET_L-01_P-001" (solid, pour order 1641): 1904.38,4431.31 1904.38,4304.44 1921.96,4286.87 2002.31,4286.87 2060.99,4228.19 2231.91,4228.19 2263.2,4259.48 2263.2,4474.28 2238.11,4499.37 2046.07,4499.37 1995.98,4449.28 1922.35,4449.28
VIN on L10-INT 5 "NONET_L-01_P-001" (solid, pour order 1640): 1871.48,4290.26 1871.48,4417.13 1853.91,4434.7 1773.55,4434.7 1714.88,4493.38 1487.5,4493.38 1461.52,4467.39 1461.52,4252.8 1492.12,4222.2 1729.79,4222.2 1779.88,4272.29 1853.52,4272.29
VOUT on L10-INT 5 "NONET_L-01_P-001" (solid, pour order 1639): 1904.38,5375.51 1904.38,5248.64 1921.96,5231.06 2002.31,5231.06 2060.99,5172.39 2231.91,5172.39 2263.2,5203.67 2263.2,5418.48 2238.11,5443.56 2046.07,5443.56 1995.98,5393.48 1922.35,5393.48
VIN on L10-INT 5 "NONET_L-01_P-001" (solid, pour order 1638): 1871.48,5234.45 1871.48,5361.32 1853.91,5378.9 1773.55,5378.9 1714.88,5437.57 1487.5,5437.57 1461.52,5411.59 1461.52,5197 1492.12,5166.4 1729.79,5166.4 1779.88,5216.49 1853.52,5216.49
CSA_IN- on L10-INT 5 "L10-INT_5_CSA_IN-_P1767" (solid, remove dead copper, pour order 1767): 3332.59,5884.82 3304.22,5856.44 2882.86,5856.44 2858.8,5880.5 2858.8,7380.82 2873.03,7395.05 3312.43,7395.05 3332.59,7374.88
QGND on L11-INT 6 "L11-INT_6_QGND_P1780" (solid, remove dead copper, pour order 1780): 3367.03,7413.9 3388.65,7435.52 3388.65,7708.27 3372.41,7724.51 246.08,7724.51 29.23,7507.66 29.23,6081.96 82.37,6031.04 2585.13,6031.04 2654.12,6100.03 2654.12,7391.34 2676.68,7413.9
PGND on L11-INT 6 "L11-INT_6_PGND_P1779" (solid, remove dead copper, pour order 1779): 26.96,56.7 55.66,28 3703.56,28 3746.15,70.6 3746.15,1660.54 3715.79,1690.9 48.73,1690.9 26.96,1669.12
PGND on L11-INT 6 "L11-INT_6_PGND_P1773" (solid, remove dead copper, pour order 1773): 24.73,63.23 64.06,23.9 3692.54,23.9 3748.76,80.11 3748.76,1622.96 3680.82,1690.9 69.02,1690.9 24.73,1646.61
VIN on L11-INT 6 "L11-INT_6_VIN_P1778" (solid, remove dead copper, pour order 1778): 76.04,1723.9 1835.41,1723.9 1873.32,1761.8 1873.32,5995.34 1850.52,6018.73 73.45,6018.73 28.38,5973.66 28.38,1771.56
VOUT on L11-INT 6 "L11-INT_6_VOUT_P1777" (solid, remove dead copper, pour order 1777): 1931.67,6018 2533.6,6018 2737.97,5813.63 3701.12,5813.63 3753.65,5761.09 3753.65,1751.37 3726.18,1723.9 1941.76,1723.9 1904.28,1761.37 1904.28,5990.62
VOUT on L11-INT 6 "L11-INT_6_VOUT_P1774" (solid, remove dead copper, pour order 1774): 3380.94,7387.36 3721.81,7387.36 3744.28,7364.89 3744.28,5854.53 3713.49,5823.73 3391.9,5823.73 3359.28,5856.35 3359.28,7365.7
VOUT on L11-INT 6 "NONET_L-01_P-001" (solid, pour order 1649): 1904.38,3487.12 1904.38,3360.24 1921.96,3342.67 2002.31,3342.67 2060.99,3284 2231.91,3284 2263.2,3315.28 2263.2,3530.08 2238.11,3555.17 2046.07,3555.17 1995.98,3505.08 1922.35,3505.08
PGND on L11-INT 6 "L11-INT_6_PGND_P1776" (solid, remove dead copper, pour order 1776): 2843.98,5931.08 2823.92,5911.02 2681.1,5911.02 2669.47,5922.65 2669.47,7376.14 2688.81,7395.49 2821.74,7395.49 2843.98,7373.25
VOUT on L11-INT 6 "NONET_L-01_P-001" (solid, pour order 1651): 1904.38,2542.92 1904.38,2416.05 1921.96,2398.48 2002.31,2398.48 2060.99,2339.8 2231.91,2339.8 2263.2,2371.09 2263.2,2585.89 2238.11,2610.98 2046.07,2610.98 1995.98,2560.89 1922.35,2560.89
VIN on L11-INT 6 "NONET_L-01_P-001" (solid, pour order 1650): 1871.48,2401.86 1871.48,2528.74 1853.91,2546.31 1773.55,2546.31 1714.88,2604.98 1487.5,2604.98 1461.52,2579 1461.52,2364.41 1492.12,2333.81 1729.79,2333.81 1779.88,2383.9 1853.52,2383.9
VIN on L11-INT 6 "NONET_L-01_P-001" (solid, pour order 1648): 1871.48,3346.06 1871.48,3472.93 1853.91,3490.51 1773.55,3490.51 1714.88,3549.18 1487.5,3549.18 1461.52,3523.2 1461.52,3308.61 1492.12,3278.01 1729.79,3278.01 1779.88,3328.09 1853.52,3328.09
VOUT on L11-INT 6 "NONET_L-01_P-001" (solid, pour order 1647): 1904.38,4431.31 1904.38,4304.44 1921.96,4286.87 2002.31,4286.87 2060.99,4228.19 2231.91,4228.19 2263.2,4259.48 2263.2,4474.28 2238.11,4499.37 2046.07,4499.37 1995.98,4449.28 1922.35,4449.28
VIN on L11-INT 6 "NONET_L-01_P-001" (solid, pour order 1646): 1871.48,4290.26 1871.48,4417.13 1853.91,4434.7 1773.55,4434.7 1714.88,4493.38 1487.5,4493.38 1461.52,4467.39 1461.52,4252.8 1492.12,4222.2 1729.79,4222.2 1779.88,4272.29 1853.52,4272.29
VOUT on L11-INT 6 "NONET_L-01_P-001" (solid, pour order 1645): 1904.38,5375.51 1904.38,5248.64 1921.96,5231.06 2002.31,5231.06 2060.99,5172.39 2231.91,5172.39 2263.2,5203.67 2263.2,5418.48 2238.11,5443.56 2046.07,5443.56 1995.98,5393.48 1922.35,5393.48
VIN on L11-INT 6 "NONET_L-01_P-001" (solid, pour order 1484): 1871.48,5234.45 1871.48,5361.32 1853.91,5378.9 1773.55,5378.9 1714.88,5437.57 1487.5,5437.57 1461.52,5411.59 1461.52,5197 1492.12,5166.4 1729.79,5166.4 1779.88,5216.49 1853.52,5216.49
CSA_IN- on L11-INT 6 "L11-INT_6_CSA_IN-_P1775" (solid, remove dead copper, pour order 1775): 3332.59,5884.82 3304.22,5856.44 2882.86,5856.44 2858.8,5880.5 2858.8,7380.82 2873.03,7395.05 3312.43,7395.05 3332.59,7374.88
QGND on L12-Power 5 "L12-POWER_5_QGND_P1788" (solid, remove dead copper, pour order 1788): 3359.28,7413.9 3388.03,7442.64 3388.03,7710.15 3373.67,7724.51 226.93,7724.51 29.23,7526.81 29.23,6081.96 82.37,6031.04 2585.13,6031.04 2654.12,6100.03 2654.12,7391.34 2676.68,7413.9
PGND on L12-Power 5 "L12-POWER_5_PGND_P1787" (solid, remove dead copper, pour order 1787): 26.96,56.7 55.66,28 3703.56,28 3746.15,70.6 3746.15,1660.54 3715.79,1690.9 48.73,1690.9 26.96,1669.12
VIN on L12-Power 5 "L12-POWER_5_VIN_P1786" (solid, remove dead copper, pour order 1786): 76.04,1723.9 1835.41,1723.9 1873.32,1761.8 1873.32,5995.34 1850.52,6018.73 73.45,6018.73 28.38,5973.66 28.38,1771.56
VOUT on L12-Power 5 "L12-POWER_5_VOUT_P1785" (solid, remove dead copper, pour order 1785): 1931.67,6018 2533.6,6018 2737.97,5813.63 3701.12,5813.63 3753.65,5761.09 3753.65,1751.37 3726.18,1723.9 1941.76,1723.9 1904.28,1761.37 1904.28,5990.62
VOUT on L12-Power 5 "L12-POWER_5_VOUT_P1782" (solid, remove dead copper, pour order 1782): 3380.94,7387.36 3721.81,7387.36 3744.28,7364.89 3744.28,5854.53 3713.49,5823.73 3391.9,5823.73 3359.28,5856.35 3359.28,7365.7
VOUT on L12-Power 5 "NONET_L-01_P-001" (solid, pour order 1657): 1904.38,3487.12 1904.38,3360.24 1921.96,3342.67 2002.31,3342.67 2060.99,3284 2231.91,3284 2263.2,3315.28 2263.2,3530.08 2238.11,3555.17 2046.07,3555.17 1995.98,3505.08 1922.35,3505.08
PGND on L12-Power 5 "L12-POWER_5_PGND_P1784" (solid, remove dead copper, pour order 1784): 2843.98,5931.08 2823.92,5911.02 2681.1,5911.02 2669.47,5922.65 2669.47,7376.14 2688.81,7395.49 2821.74,7395.49 2843.98,7373.25
VOUT on L12-Power 5 "NONET_L-01_P-001" (solid, pour order 1781): 1904.38,2542.92 1904.38,2416.05 1921.96,2398.48 2002.31,2398.48 2060.99,2339.8 2231.91,2339.8 2263.2,2371.09 2263.2,2585.89 2238.11,2610.98 2046.07,2610.98 1995.98,2560.89 1922.35,2560.89
VIN on L12-Power 5 "NONET_L-01_P-001" (solid, pour order 1658): 1871.48,2401.86 1871.48,2528.74 1853.91,2546.31 1773.55,2546.31 1714.88,2604.98 1487.5,2604.98 1461.52,2579 1461.52,2364.41 1492.12,2333.81 1729.79,2333.81 1779.88,2383.9 1853.52,2383.9
VIN on L12-Power 5 "NONET_L-01_P-001" (solid, pour order 1656): 1871.48,3346.06 1871.48,3472.93 1853.91,3490.51 1773.55,3490.51 1714.88,3549.18 1487.5,3549.18 1461.52,3523.2 1461.52,3308.61 1492.12,3278.01 1729.79,3278.01 1779.88,3328.09 1853.52,3328.09
VOUT on L12-Power 5 "NONET_L-01_P-001" (solid, pour order 1655): 1904.38,4431.31 1904.38,4304.44 1921.96,4286.87 2002.31,4286.87 2060.99,4228.19 2231.91,4228.19 2263.2,4259.48 2263.2,4474.28 2238.11,4499.37 2046.07,4499.37 1995.98,4449.28 1922.35,4449.28
VIN on L12-Power 5 "NONET_L-01_P-001" (solid, pour order 1654): 1871.48,4290.26 1871.48,4417.13 1853.91,4434.7 1773.55,4434.7 1714.88,4493.38 1487.5,4493.38 1461.52,4467.39 1461.52,4252.8 1492.12,4222.2 1729.79,4222.2 1779.88,4272.29 1853.52,4272.29
VOUT on L12-Power 5 "NONET_L-01_P-001" (solid, pour order 1653): 1904.38,5375.51 1904.38,5248.64 1921.96,5231.06 2002.31,5231.06 2060.99,5172.39 2231.91,5172.39 2263.2,5203.67 2263.2,5418.48 2238.11,5443.56 2046.07,5443.56 1995.98,5393.48 1922.35,5393.48
VIN on L12-Power 5 "NONET_L-01_P-001" (solid, pour order 1652): 1871.48,5234.45 1871.48,5361.32 1853.91,5378.9 1773.55,5378.9 1714.88,5437.57 1487.5,5437.57 1461.52,5411.59 1461.52,5197 1492.12,5166.4 1729.79,5166.4 1779.88,5216.49 1853.52,5216.49
CSA_IN- on L12-Power 5 "L12-POWER_5_CSA_IN-_P1783" (solid, remove dead copper, pour order 1783): 3332.59,5884.82 3304.22,5856.44 2882.86,5856.44 2858.8,5880.5 2858.8,7380.82 2873.03,7395.05 3312.43,7395.05 3332.59,7374.88
QGND on L13-Power 6 "L13-POWER_6_QGND_P1796" (solid, remove dead copper, pour order 1796): 3312.43,7413.9 3386.33,7487.8 3386.33,7711.85 3369.28,7728.9 231.32,7728.9 29.23,7526.81 29.23,6081.96 82.37,6031.04 2585.13,6031.04 2654.12,6100.03 2654.12,7391.34 2676.68,7413.9
PGND on L13-Power 6 "L13-POWER_6_PGND_P1795" (solid, remove dead copper, pour order 1795): 26.96,56.7 55.66,28 3703.56,28 3746.15,70.6 3746.15,1660.54 3715.79,1690.9 48.73,1690.9 26.96,1669.12
PGND on L13-Power 6 "L13-POWER_6_PGND_P1789" (solid, remove dead copper, pour order 1789): 33.6,96.52 106.22,23.9 3658.07,23.9 3732.99,98.82 3732.99,1656.25 3698.34,1690.9 70.73,1690.9 33.6,1653.76
VIN on L13-Power 6 "L13-POWER_6_VIN_P1794" (solid, remove dead copper, pour order 1794): 76.04,1723.9 1835.41,1723.9 1873.32,1761.8 1873.32,5995.34 1850.52,6018.73 73.45,6018.73 28.38,5973.66 28.38,1771.56
VOUT on L13-Power 6 "L13-POWER_6_VOUT_P1793" (solid, remove dead copper, pour order 1793): 1931.67,6018 2533.6,6018 2737.97,5813.63 3701.12,5813.63 3753.65,5761.09 3753.65,1751.37 3726.18,1723.9 1941.76,1723.9 1904.28,1761.37 1904.28,5990.62
VOUT on L13-Power 6 "L13-POWER_6_VOUT_P1790" (solid, remove dead copper, pour order 1790): 3380.94,7387.36 3721.81,7387.36 3744.28,7364.89 3744.28,5854.53 3713.49,5823.73 3391.9,5823.73 3359.28,5856.35 3359.28,7365.7
VOUT on L13-Power 6 "NONET_L-01_P-001" (solid, pour order 1663): 1904.38,3487.12 1904.38,3360.24 1921.96,3342.67 2002.31,3342.67 2060.99,3284 2231.91,3284 2263.2,3315.28 2263.2,3530.08 2238.11,3555.17 2046.07,3555.17 1995.98,3505.08 1922.35,3505.08
PGND on L13-Power 6 "L13-POWER_6_PGND_P1792" (solid, remove dead copper, pour order 1792): 2843.98,5931.08 2823.92,5911.02 2681.1,5911.02 2669.47,5922.65 2669.47,7376.14 2688.81,7395.49 2821.74,7395.49 2843.98,7373.25
VOUT on L13-Power 6 "NONET_L-01_P-001" (solid, pour order 1665): 1904.38,2542.92 1904.38,2416.05 1921.96,2398.48 2002.31,2398.48 2060.99,2339.8 2231.91,2339.8 2263.2,2371.09 2263.2,2585.89 2238.11,2610.98 2046.07,2610.98 1995.98,2560.89 1922.35,2560.89
VIN on L13-Power 6 "NONET_L-01_P-001" (solid, pour order 1664): 1871.48,2401.86 1871.48,2528.74 1853.91,2546.31 1773.55,2546.31 1714.88,2604.98 1487.5,2604.98 1461.52,2579 1461.52,2364.41 1492.12,2333.81 1729.79,2333.81 1779.88,2383.9 1853.52,2383.9
VIN on L13-Power 6 "NONET_L-01_P-001" (solid, pour order 1662): 1871.48,3346.06 1871.48,3472.93 1853.91,3490.51 1773.55,3490.51 1714.88,3549.18 1487.5,3549.18 1461.52,3523.2 1461.52,3308.61 1492.12,3278.01 1729.79,3278.01 1779.88,3328.09 1853.52,3328.09
VOUT on L13-Power 6 "NONET_L-01_P-001" (solid, pour order 1661): 1904.38,4431.31 1904.38,4304.44 1921.96,4286.87 2002.31,4286.87 2060.99,4228.19 2231.91,4228.19 2263.2,4259.48 2263.2,4474.28 2238.11,4499.37 2046.07,4499.37 1995.98,4449.28 1922.35,4449.28
VIN on L13-Power 6 "NONET_L-01_P-001" (solid, pour order 1660): 1871.48,4290.26 1871.48,4417.13 1853.91,4434.7 1773.55,4434.7 1714.88,4493.38 1487.5,4493.38 1461.52,4467.39 1461.52,4252.8 1492.12,4222.2 1729.79,4222.2 1779.88,4272.29 1853.52,4272.29
VOUT on L13-Power 6 "NONET_L-01_P-001" (solid, pour order 1659): 1904.38,5375.51 1904.38,5248.64 1921.96,5231.06 2002.31,5231.06 2060.99,5172.39 2231.91,5172.39 2263.2,5203.67 2263.2,5418.48 2238.11,5443.56 2046.07,5443.56 1995.98,5393.48 1922.35,5393.48
VIN on L13-Power 6 "NONET_L-01_P-001" (solid, pour order 1514): 1871.48,5234.45 1871.48,5361.32 1853.91,5378.9 1773.55,5378.9 1714.88,5437.57 1487.5,5437.57 1461.52,5411.59 1461.52,5197 1492.12,5166.4 1729.79,5166.4 1779.88,5216.49 1853.52,5216.49
CSA_IN- on L13-Power 6 "L13-POWER_6_CSA_IN-_P1791" (solid, remove dead copper, pour order 1791): 3332.59,5884.82 3304.22,5856.44 2882.86,5856.44 2858.8,5880.5 2858.8,7380.82 2873.03,7395.05 3312.43,7395.05 3332.59,7374.88
QGND on L14-Power 7 "L14-POWER_7_QGND_P1804" (solid, remove dead copper, pour order 1804): 3359.28,7413.9 3388.03,7442.64 3388.03,7710.15 3373.67,7724.51 226.93,7724.51 29.23,7526.81 29.23,6081.96 82.37,6031.04 2585.13,6031.04 2654.12,6100.03 2654.12,7391.34 2676.68,7413.9
PGND on L14-Power 7 "L14-POWER_7_PGND_P1803" (solid, remove dead copper, pour order 1803): 26.96,56.7 55.66,28 3703.56,28 3746.15,70.6 3746.15,1660.54 3715.79,1690.9 48.73,1690.9 26.96,1669.12
VIN on L14-Power 7 "L14-POWER_7_VIN_P1802" (solid, remove dead copper, pour order 1802): 76.04,1723.9 1835.41,1723.9 1873.32,1761.8 1873.32,5995.34 1850.52,6018.73 73.45,6018.73 28.38,5973.66 28.38,1771.56
VOUT on L14-Power 7 "L14-POWER_7_VOUT_P1801" (solid, remove dead copper, pour order 1801): 1931.67,6018 2533.6,6018 2737.97,5813.63 3701.12,5813.63 3753.65,5761.09 3753.65,1751.37 3726.18,1723.9 1941.76,1723.9 1904.28,1761.37 1904.28,5990.62
VOUT on L14-Power 7 "L14-POWER_7_VOUT_P1798" (solid, remove dead copper, pour order 1798): 3380.94,7387.36 3721.81,7387.36 3744.28,7364.89 3744.28,5854.53 3713.49,5823.73 3391.9,5823.73 3359.28,5856.35 3359.28,7365.7
VOUT on L14-Power 7 "NONET_L-01_P-001" (solid, pour order 1671): 1904.38,3487.12 1904.38,3360.24 1921.96,3342.67 2002.31,3342.67 2060.99,3284 2231.91,3284 2263.2,3315.28 2263.2,3530.08 2238.11,3555.17 2046.07,3555.17 1995.98,3505.08 1922.35,3505.08
PGND on L14-Power 7 "L14-POWER_7_PGND_P1800" (solid, remove dead copper, pour order 1800): 2843.98,5931.08 2823.92,5911.02 2681.1,5911.02 2669.47,5922.65 2669.47,7376.14 2688.81,7395.49 2821.74,7395.49 2843.98,7373.25
VOUT on L14-Power 7 "NONET_L-01_P-001" (solid, pour order 1797): 1904.38,2542.92 1904.38,2416.05 1921.96,2398.48 2002.31,2398.48 2060.99,2339.8 2231.91,2339.8 2263.2,2371.09 2263.2,2585.89 2238.11,2610.98 2046.07,2610.98 1995.98,2560.89 1922.35,2560.89
VIN on L14-Power 7 "NONET_L-01_P-001" (solid, pour order 1672): 1871.48,2401.86 1871.48,2528.74 1853.91,2546.31 1773.55,2546.31 1714.88,2604.98 1487.5,2604.98 1461.52,2579 1461.52,2364.41 1492.12,2333.81 1729.79,2333.81 1779.88,2383.9 1853.52,2383.9
VIN on L14-Power 7 "NONET_L-01_P-001" (solid, pour order 1670): 1871.48,3346.06 1871.48,3472.93 1853.91,3490.51 1773.55,3490.51 1714.88,3549.18 1487.5,3549.18 1461.52,3523.2 1461.52,3308.61 1492.12,3278.01 1729.79,3278.01 1779.88,3328.09 1853.52,3328.09
VOUT on L14-Power 7 "NONET_L-01_P-001" (solid, pour order 1669): 1904.38,4431.31 1904.38,4304.44 1921.96,4286.87 2002.31,4286.87 2060.99,4228.19 2231.91,4228.19 2263.2,4259.48 2263.2,4474.28 2238.11,4499.37 2046.07,4499.37 1995.98,4449.28 1922.35,4449.28
VIN on L14-Power 7 "NONET_L-01_P-001" (solid, pour order 1668): 1871.48,4290.26 1871.48,4417.13 1853.91,4434.7 1773.55,4434.7 1714.88,4493.38 1487.5,4493.38 1461.52,4467.39 1461.52,4252.8 1492.12,4222.2 1729.79,4222.2 1779.88,4272.29 1853.52,4272.29
VOUT on L14-Power 7 "NONET_L-01_P-001" (solid, pour order 1667): 1904.38,5375.51 1904.38,5248.64 1921.96,5231.06 2002.31,5231.06 2060.99,5172.39 2231.91,5172.39 2263.2,5203.67 2263.2,5418.48 2238.11,5443.56 2046.07,5443.56 1995.98,5393.48 1922.35,5393.48
VIN on L14-Power 7 "NONET_L-01_P-001" (solid, pour order 1666): 1871.48,5234.45 1871.48,5361.32 1853.91,5378.9 1773.55,5378.9 1714.88,5437.57 1487.5,5437.57 1461.52,5411.59 1461.52,5197 1492.12,5166.4 1729.79,5166.4 1779.88,5216.49 1853.52,5216.49
CSA_IN- on L14-Power 7 "L14-POWER_7_CSA_IN-_P1799" (solid, remove dead copper, pour order 1799): 3332.59,5884.82 3304.22,5856.44 2882.86,5856.44 2858.8,5880.5 2858.8,7380.82 2873.03,7395.05 3312.43,7395.05 3332.59,7374.88
QGND on L15-Power 8 "L15-POWER_8_QGND_P1812" (solid, remove dead copper, pour order 1812): 34.28,7528.9 229.89,7724.51 3373.67,7724.51 3388.03,7710.15 3388.03,7424.03 3375.32,7411.32 2669.86,7411.32 2644.28,7385.74 2644.28,6133.31 2562.57,6051.6 122.53,6051.6 34.28,6139.85
PGND on L15-Power 8 "NONET_L-01_P-001" (solid, remove dead copper, pour order 1811): 88.28,6038.29 2560.87,6038.29 2768.57,5830.59 3199.03,5830.59 3272.92,5756.7 3703.33,5756.7 3746.33,5713.7 3746.33,64.32 3710.91,28.9 82.38,28.9 33.94,77.34 33.94,5984.68
VOUT on L15-Power 8 "L15-POWER_8_VOUT_P1808" (solid, remove dead copper, pour order 1808): 3295.94,7378.5 3717.7,7378.5 3746.33,7349.87 3746.33,5797.42 3715.84,5766.92 3307.15,5766.92 3279.28,5794.79 3279.28,7361.85
VOUT on L15-Power 8 "L8_BOT_[PWR]_NONET_P-001" (solid, remove dead copper, pour order 1805): 3407.49,3323.9 3407.49,2867.47 3372.2,2832.18 2581.76,2832.18 2539.6,2874.34 2539.6,3328.09 2570.4,3358.9 3372.49,3358.9
VIN on L15-Power 8 "L8_BOT_[PWR]_NONET_P-001" (solid, remove dead copper, pour order 1683): 369.28,2860.51 369.28,3316.93 404.58,3352.23 1195.02,3352.23 1237.18,3310.07 1237.18,2856.31 1206.37,2825.51 404.28,2825.51
VOUT on L15-Power 8 "NONET_L-01_P-001" (solid, pour order 1678): 1904.38,3487.12 1904.38,3360.24 1921.96,3342.67 2002.31,3342.67 2060.99,3284 2231.91,3284 2263.2,3315.28 2263.2,3530.08 2238.11,3555.17 2046.07,3555.17 1995.98,3505.08 1922.35,3505.08
PGND on L15-Power 8 "L15-POWER_8_PGND_P1810" (solid, remove dead copper, pour order 1810): 2832.71,5950.81 2825.33,5943.43 2665.36,5943.43 2658.2,5950.59 2658.2,7383.68 2674.25,7399.73 2814.57,7399.73 2832.71,7381.59
VOUT on L15-Power 8 "NONET_L-01_P-001" (solid, pour order 1680): 1904.38,2542.92 1904.38,2416.05 1921.96,2398.48 2002.31,2398.48 2060.99,2339.8 2231.91,2339.8 2263.2,2371.09 2263.2,2585.89 2238.11,2610.98 2046.07,2610.98 1995.98,2560.89 1922.35,2560.89
VIN on L15-Power 8 "NONET_L-01_P-001" (solid, pour order 1679): 1871.48,2401.86 1871.48,2528.74 1853.91,2546.31 1773.55,2546.31 1714.88,2604.98 1487.5,2604.98 1461.52,2579 1461.52,2364.41 1492.12,2333.81 1729.79,2333.81 1779.88,2383.9 1853.52,2383.9
VIN on L15-Power 8 "NONET_L-01_P-001" (solid, pour order 1677): 1871.48,3346.06 1871.48,3472.93 1853.91,3490.51 1773.55,3490.51 1714.88,3549.18 1487.5,3549.18 1461.52,3523.2 1461.52,3308.61 1492.12,3278.01 1729.79,3278.01 1779.88,3328.09 1853.52,3328.09
VOUT on L15-Power 8 "NONET_L-01_P-001" (solid, pour order 1676): 1904.38,4431.31 1904.38,4304.44 1921.96,4286.87 2002.31,4286.87 2060.99,4228.19 2231.91,4228.19 2263.2,4259.48 2263.2,4474.28 2238.11,4499.37 2046.07,4499.37 1995.98,4449.28 1922.35,4449.28
VIN on L15-Power 8 "NONET_L-01_P-001" (solid, pour order 1675): 1871.48,4290.26 1871.48,4417.13 1853.91,4434.7 1773.55,4434.7 1714.88,4493.38 1487.5,4493.38 1461.52,4467.39 1461.52,4252.8 1492.12,4222.2 1729.79,4222.2 1779.88,4272.29 1853.52,4272.29
VOUT on L15-Power 8 "NONET_L-01_P-001" (solid, pour order 1674): 1904.38,5375.51 1904.38,5248.64 1921.96,5231.06 2002.31,5231.06 2060.99,5172.39 2231.91,5172.39 2263.2,5203.67 2263.2,5418.48 2238.11,5443.56 2046.07,5443.56 1995.98,5393.48 1922.35,5393.48
VIN on L15-Power 8 "NONET_L-01_P-001" (solid, pour order 1673): 1871.48,5234.45 1871.48,5361.32 1853.91,5378.9 1773.55,5378.9 1714.88,5437.57 1487.5,5437.57 1461.52,5411.59 1461.52,5197 1492.12,5166.4 1729.79,5166.4 1779.88,5216.49 1853.52,5216.49
CSA_IN- on L15-Power 8 "L15-POWER_8_CSA_IN-_P1809" (solid, remove dead copper, pour order 1809): 3263.32,5880.3 3229.51,5846.5 2881.2,5846.5 2858.8,5868.9 2858.8,7383.14 2869.43,7393.77 3240.95,7393.77 3263.32,7371.4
